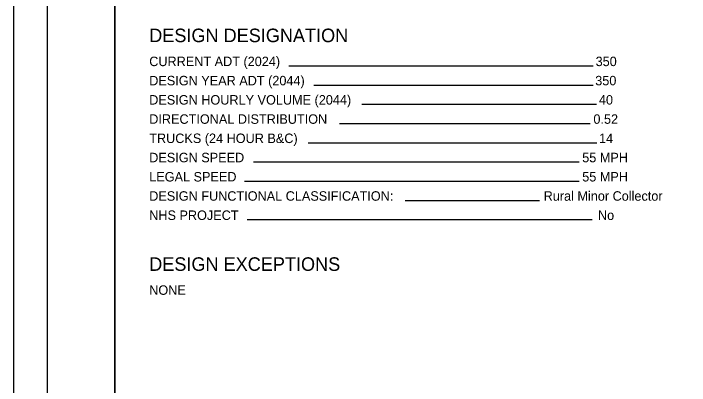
# Model space of a CAD drawing. Extents: x -15 to 405, y -40 to 87.
# Drawn here: x -0.01 to 9.99, y 5.51 to 11.01 of the extents above; entities that cross this region are included whole.
import ezdxf

# ---------------------------------------------------------------- set-up
doc = ezdxf.new("R2010")
doc.units = 0
for name, color, linetype in [('GM_X_County', 7, 'Continuous'), ('GM_X_Section', 7, 'Continuous'), ('GM_X_Township', 7, 'Continuous')]:
    doc.layers.add(name, color=color, linetype=linetype)

msp = doc.modelspace()

# ---------------------------------------------------------------- linework, layer by layer
at = {"layer": 'GM_X_County'}
for points in [[(0.4934, 21.5), (1.4934, 21.5), (1.4934, 0.5), (0.4934, 0.5)], [(1.4934, 21.5), (33.4934, 21.5), (33.4934, 0.5), (1.4934, 0.5)]]:
    msp.add_lwpolyline(points, close=True, dxfattribs=at)
at = {"layer": 'GM_X_Section'}
msp.add_lwpolyline([(-0.0066, 0), (33.9934, 0), (33.9934, 22), (-0.0066, 22)], close=True, dxfattribs=at)
at = {"layer": 'GM_X_Township'}
for p, q in [((8.5666, 10.2298), (4.0636, 10.2298)), ((8.5666, 9.9457), (4.4336, 9.9457)), ((8.6131, 9.6616), (5.1452, 9.6616)), ((8.5205, 9.3775), (4.8131, 9.3775)), ((8.6191, 9.0934), (4.3482, 9.0934)), ((8.3555, 8.8093), (3.5417, 8.8093)), ((8.3555, 8.5252), (3.4089, 8.5252)), ((7.7708, 8.2411), (5.7846, 8.2411)), ((8.5496, 7.957), (3.4468, 7.957))]:
    msp.add_line(p, q, dxfattribs=at)

# ---------------------------------------------------------------- texts
for s, height, p in [('DESIGN DESIGNATION', 0.2, (2, 10.5837)), ('CURRENT ADT (2024)', 0.14, (2, 10.2298)), ('350', 0.14, (8.6004, 10.2298)), ('DESIGN YEAR ADT (2044)', 0.14, (2, 9.9457)), ('350', 0.14, (8.5948, 9.9457)), ('DESIGN HOURLY VOLUME (2044)', 0.14, (2, 9.6616)), ('40', 0.14, (8.6492, 9.6616)), ('DIRECTIONAL DISTRIBUTION', 0.14, (2, 9.3775)), ('0.52', 0.14, (8.5679, 9.3775)), ('TRUCKS (24 HOUR B&C)', 0.14, (2, 9.0934)), ('14', 0.14, (8.6512, 9.0934)), ('DESIGN SPEED', 0.14, (2, 8.8093)), ('55 MPH', 0.14, (8.4022, 8.8093)), ('LEGAL SPEED', 0.14, (2, 8.5252)), ('55 MPH', 0.14, (8.4022, 8.5252)), ('DESIGN FUNCTIONAL CLASSIFICATION:', 0.14, (2, 8.2411)), ('Rural Minor Collector', 0.14, (7.8319, 8.2411)), ('NHS PROJECT', 0.14, (2, 7.957)), ('No', 0.14, (8.6354, 7.957)), ('DESIGN EXCEPTIONS', 0.2, (2, 7.205)), ('NONE', 0.14, (2, 6.851))]:
    msp.add_text(s, height=height, dxfattribs=at).set_placement(p)

doc.saveas('drawing.dxf')
